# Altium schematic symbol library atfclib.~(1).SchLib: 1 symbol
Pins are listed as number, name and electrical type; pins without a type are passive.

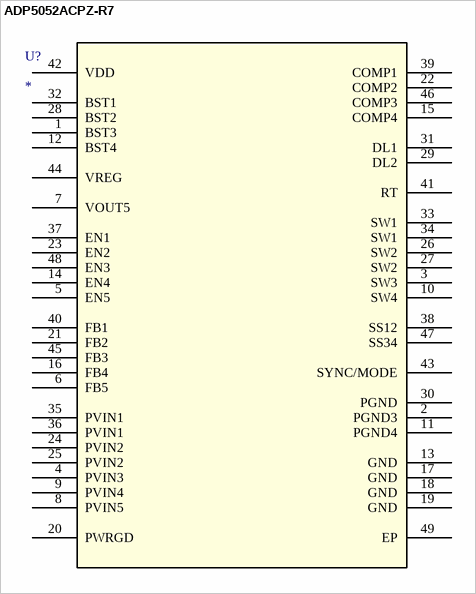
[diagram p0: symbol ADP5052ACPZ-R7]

## ADP5052ACPZ-R7
designator U?
Imported
footprint CP_48_13
pins: 1 BST3, 2 PGND3, 3 SW3, 4 PVIN3, 5 EN5, 6 FB5, 7 VOUT5, 8 PVIN5, 9 PVIN4, 10 SW4, 11 PGND4, 12 BST4, 13 GND, 14 EN4, 15 COMP4, 16 FB4, 17 GND, 18 GND, 19 GND, 20 PWRGD, 21 FB2, 22 COMP2, 23 EN2, 24 PVIN2, 25 PVIN2, 26 SW2, 27 SW2, 28 BST2, 29 DL2, 30 PGND, 31 DL1, 32 BST1, 33 SW1, 34 SW1, 35 PVIN1, 36 PVIN1, 37 EN1, 38 SS12, 39 COMP1, 40 FB1, 41 RT, 42 VDD, 43 SYNC/MODE, 44 VREG, 45 FB3, 46 COMP3, 47 SS34, 48 EN3, 49 EP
